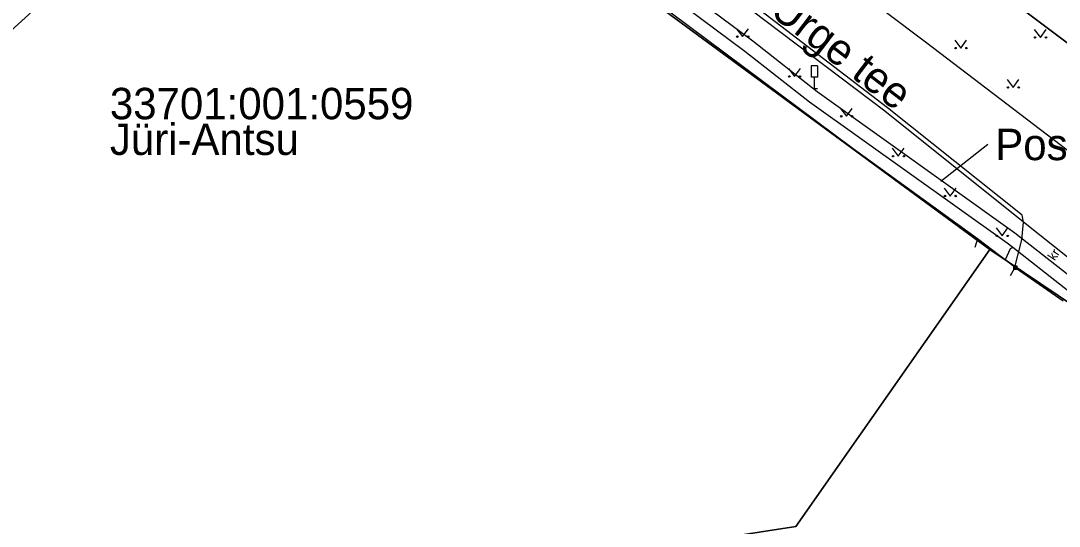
# Model space of a CAD drawing. Extents: x 554947 to 555436, y 6564938 to 6565792.
# Drawn here: x 555228.5 to 555307.9, y 6565518.6 to 6565557.2 of the extents above; entities that cross this region are included whole.
import ezdxf

# ---------------------------------------------------------------- set-up
doc = ezdxf.new("R2010")
doc.units = 0
for name, color, linetype in [('AED', 7, 'Continuous'), ('HALJASTUS', 7, 'Continuous'), ('KASUTUSALA', 7, 'Continuous'), ('LIIKLUS', 7, 'Continuous'), ('PIIR', 7, 'Continuous'), ('PR_SIDE', 7, 'Continuous'), ('TEE', 7, 'Continuous'), ('VORMISTUS_3', 7, 'Continuous')]:
    doc.layers.add(name, color=color, linetype=linetype)

msp = doc.modelspace()

# ---------------------------------------------------------------- linework, layer by layer
at = {"layer": 'AED'}
for p, q in [((555304.399, 6565538.477), (555304.399, 6565538.227)), ((555304.399, 6565538.477), (555304.649, 6565538.477)), ((555304.649, 6565538.477), (555304.649, 6565538.227)), ((555304.399, 6565538.227), (555304.649, 6565538.227)), ((555304.524, 6565538.352), (555308.195, 6565535.788))]:
    msp.add_line(p, q, dxfattribs=at)
for points in [[(555301.646, 6565540.531), (555292.158, 6565547.42), (555274.134, 6565560.859), (555261.407, 6565570.297)], [(555304.524, 6565538.352), (555301.646, 6565540.531), (555301.451, 6565539.862)]]:
    msp.add_lwpolyline(points, dxfattribs=at)
at = {"layer": 'HALJASTUS'}
for p, q in [((555283.235, 6565556.583), (555283.698, 6565555.977)), ((555283.698, 6565555.977), (555284.144, 6565556.583)), ((555305.994, 6565556.526), (555306.458, 6565555.919)), ((555306.458, 6565555.919), (555306.903, 6565556.526)), ((555299.913, 6565555.706), (555300.377, 6565555.1)), ((555300.377, 6565555.1), (555300.822, 6565555.706)), ((555287.202, 6565553.54), (555287.666, 6565552.934)), ((555287.666, 6565552.934), (555288.111, 6565553.54)), ((555303.913, 6565552.706), (555304.376, 6565552.099)), ((555304.376, 6565552.099), (555304.822, 6565552.706)), ((555291.17, 6565550.497), (555291.633, 6565549.89)), ((555291.633, 6565549.89), (555292.079, 6565550.497)), ((555295.137, 6565547.454), (555295.6, 6565546.847)), ((555295.6, 6565546.847), (555296.046, 6565547.454)), ((555299.104, 6565544.411), (555299.568, 6565543.804)), ((555299.568, 6565543.804), (555300.013, 6565544.411)), ((555303.071, 6565541.368), (555303.535, 6565540.761)), ((555303.535, 6565540.761), (555303.98, 6565541.368))]:
    msp.add_line(p, q, dxfattribs=at)
for centre in [(555283.297, 6565555.977), (555284.126, 6565555.977), (555306.057, 6565555.919), (555306.886, 6565555.919), (555299.976, 6565555.1), (555300.804, 6565555.1), (555287.265, 6565552.934), (555288.093, 6565552.934), (555303.975, 6565552.099), (555304.804, 6565552.099), (555291.232, 6565549.89), (555292.061, 6565549.89), (555295.199, 6565546.847), (555296.028, 6565546.847), (555299.166, 6565543.804), (555299.995, 6565543.804), (555303.134, 6565540.761), (555303.963, 6565540.761)]:
    msp.add_circle(centre, 0.055, dxfattribs=at)
at = {"layer": 'KASUTUSALA'}
msp.add_lwpolyline([(555330.79, 6565520.761), (555305.197, 6565537.964), (555302.6, 6565539.71), (555242.37, 6565583.94), (555238.34, 6565585.593), (555238.34, 6565584.092), (555236.34, 6565584.168), (555236.34, 6565586.946), (555231.217, 6565605.702), (555233.309, 6565605.634), (555234.35, 6565605.6), (555235.803, 6565604.987), (555234.66, 6565604.12), (555233.701, 6565604.199), (555238.103, 6565588.08), (555238.175, 6565587.82), (555243.331, 6565585.721), (555250.029, 6565580.878), (555260.82, 6565573.213), (555265.213, 6565569.964), (555284.475, 6565555.644), (555289.407, 6565551.783), (555304.515, 6565541.003), (555310.277, 6565536.492)], dxfattribs=at)
at = {"layer": 'LIIKLUS'}
for p, q in [((555288.929, 6565553.739), (555288.929, 6565552.889)), ((555289.429, 6565553.739), (555288.929, 6565553.739)), ((555289.429, 6565553.739), (555289.429, 6565552.889)), ((555289.429, 6565552.889), (555288.929, 6565552.889)), ((555289.179, 6565552.889), (555289.179, 6565551.989)), ((555289.429, 6565551.989), (555289.179, 6565551.989))]:
    msp.add_line(p, q, dxfattribs=at)
at = {"layer": 'PIIR'}
for points in [[(555374.15, 6565660.24), (555410.9, 6565638.65), (555418.94, 6565635.85), (555435.71, 6565632.72), (555428.83, 6565620.98), (555419.65, 6565609.54), (555361.56, 6565549.57), (555350.68, 6565540.44), (555343.81, 6565536.56), (555330.71, 6565538.85), (555251.24, 6565598.48), (555234.35, 6565605.6), (555223.17, 6565668.21)], [(555144.16, 6565410.6), (555124.27, 6565454.45), (555113.82, 6565475.68), (555076.76, 6565542.38), (555065.78, 6565566.7), (555060.42, 6565583.26), (555057.22, 6565600.73), (555056.61, 6565622.91), (555063.43, 6565647.29), (555114.24, 6565634), (555129.77, 6565611.2), (555130.73, 6565621.32), (555138.66, 6565615.26), (555160.12, 6565598.86), (555193.24, 6565604.68), (555193.7, 6565602.7), (555225.47, 6565605.89), (555234.35, 6565605.6), (555251.24, 6565598.48), (555330.71, 6565538.85), (555343.81, 6565536.56), (555350.68, 6565540.44), (555361.56, 6565549.57), (555393.069, 6565582.099)], [(555393.069, 6565560.972), (555353.12, 6565523.87), (555343.14, 6565512.46), (555302.6, 6565539.71), (555242.37, 6565583.94), (555179.42, 6565586.32), (555138.98, 6565580.6), (555121.18, 6565602.26), (555116.17, 6565610.5), (555109.96, 6565624.83), (555093.56, 6565628.47), (555079.04, 6565618.4), (555074.13, 6565607.82), (555075.34, 6565593.24), (555091.74, 6565551.94), (555171.91, 6565394.64), (555191.35, 6565341.19), (555195.08, 6565294.61), (555195.28, 6565271.63), (555191.64, 6565237.48)]]:
    msp.add_lwpolyline(points, dxfattribs=at)
for points in [[(555121.18, 6565602.26), (555138.98, 6565580.6), (555179.42, 6565586.32), (555242.37, 6565583.94), (555302.6, 6565539.71), (555287.77, 6565518.56), (555207.29, 6565506.14), (555200.64, 6565496.23), (555185.97, 6565502.75), (555177.68, 6565506.44), (555171.49, 6565510.85), (555162.05, 6565514.45), (555140.65, 6565513.25), (555139.49, 6565523.98), (555139.26, 6565529.51), (555141.68, 6565537.52), (555139.64, 6565543.1), (555131.01, 6565550.06), (555126.35, 6565558.74), (555119.63, 6565564.84), (555105.26, 6565587.71), (555099.5, 6565594.91), (555116.17, 6565610.5)], [(555153.01, 6565448.47), (555161.15, 6565451.45), (555173.66, 6565456.03), (555207.29, 6565506.14), (555287.77, 6565518.56), (555302.6, 6565539.71), (555343.14, 6565512.46), (555319.44, 6565481.04), (555323.07, 6565461.26), (555312.9, 6565433.84), (555316.84, 6565372.52), (555318.72, 6565342.57), (555320.51, 6565314.61), (555303.13, 6565302.54), (555208.78, 6565303.3), (555205.15, 6565297.11), (555200.72, 6565310.3), (555206.9, 6565339.44), (555221.23, 6565376.06), (555216.83, 6565392.35), (555207.22, 6565406.57)]]:
    msp.add_lwpolyline(points, close=True, dxfattribs=at)
at = {"layer": 'PR_SIDE'}
for points in [[(555309.355, 6565535.944), (555304.351, 6565539.861), (555303.916, 6565540.202), (555288.808, 6565550.982), (555283.868, 6565554.848), (555264.618, 6565569.161), (555260.234, 6565572.403), (555249.446, 6565580.065), (555242.843, 6565584.84), (555237.34, 6565587.08), (555232.399, 6565605.169), (555232.137, 6565606.132)], [(555237.34, 6565587.08), (555237.34, 6565565.16), (555226.585, 6565555.364), (555203.636, 6565543.731), (555203.636, 6565538.53), (555204.984, 6565533.828), (555204.645, 6565532.63)], [(555304.351, 6565539.861), (555304.147, 6565539.781), (555303.763, 6565538.928), (555303.763, 6565538.928)]]:
    msp.add_lwpolyline(points, dxfattribs=at)
at = {"layer": 'TEE'}
for points in [[(555309.906, 6565538.03), (555305.168, 6565541.808), (555305.066, 6565542.334), (555294.766, 6565550.531), (555276.823, 6565564.276), (555265.732, 6565572.927), (555259.684, 6565577.587), (555254.787, 6565581.289), (555247.931, 6565586.532), (555243.893, 6565589.125), (555239.934, 6565591.048), (555235.042, 6565592.642), (555234.652, 6565590.428), (555233.978, 6565588.723)], [(555272.683, 6565590.134), (555271.484, 6565588.076), (555270.516, 6565586.416), (555269.723, 6565584.609), (555268.981, 6565582.24), (555268.55, 6565578.954), (555269.504, 6565576.952), (555281.044, 6565568.103), (555297.768, 6565555.508), (555316.66, 6565541.129), (555323.074, 6565536.252), (555328.036, 6565533.009), (555332.837, 6565530.879), (555337.611, 6565529.695), (555343.363, 6565529.946), (555348.456, 6565531.532), (555353.801, 6565534.677), (555358.561, 6565538.499)], [(555304.166, 6565537.744), (555304.47, 6565538.257), (555305.035, 6565540.465), (555305.168, 6565541.808), (555294.581, 6565550.293), (555276.533, 6565563.926), (555265.084, 6565572.259), (555259.201, 6565577.119), (555257.995, 6565576.697)]]:
    msp.add_lwpolyline(points, dxfattribs=at)
at = {"layer": 'VORMISTUS_3'}
msp.add_line((555298.838, 6565544.939), (555302.438, 6565547.771), dxfattribs=at)

# ---------------------------------------------------------------- texts
at = {"layer": 'PIIR'}
msp.add_text('11202 Vaida-Urge tee', height=2.4, rotation=322.58974, dxfattribs=at).set_placement((555270.504, 6565569.319))
for s, p in [('33701:001:0559', (555235.33, 6565549.665)), ('Jüri-Antsu', (555235.33, 6565546.942))]:
    msp.add_text(s, height=2.4, dxfattribs=at).set_placement(p)
at = {"layer": 'TEE'}
msp.add_text('kr', height=0.7, rotation=57.34148, dxfattribs=at).set_placement((555307.557, 6565538.819))
at = {"layer": 'VORMISTUS_3'}
msp.add_text('Pos 2', height=2.4, dxfattribs=at).set_placement((555303.012, 6565546.544))

doc.saveas('drawing.dxf')
